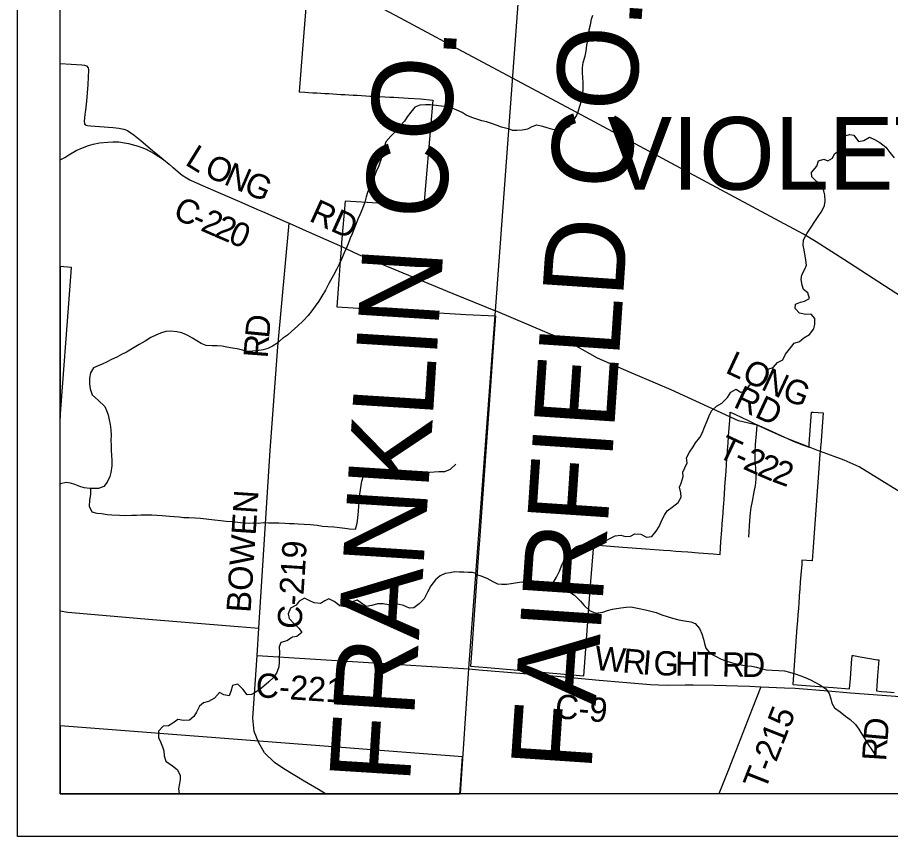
# Model space of a CAD drawing. Extents: x 0 to 34, y 0 to 26.1.
# Drawn here: x 23.417 to 25.464, y 14 to 15.919 of the extents above; entities that cross this region are included whole.
import ezdxf

# ---------------------------------------------------------------- set-up
doc = ezdxf.new("R2010")
doc.units = 0
for name, color, linetype in [('GM_X_City_Street', 7, 'Continuous'), ('GM_X_County', 7, 'Continuous'), ('GM_X_County_Road', 7, 'Continuous'), ('GM_X_County_Road_Text', 7, 'Continuous'), ('GM_X_County_Text', 7, 'Continuous'), ('GM_X_Minor_River', 7, 'Continuous'), ('GM_X_Rail_Line', 7, 'Continuous'), ('GM_X_Section', 7, 'Continuous'), ('GM_X_Township_Road', 7, 'Continuous'), ('GM_X_Township_Road_Text', 7, 'Continuous'), ('GM_X_Township_Text', 7, 'Continuous'), ('SC_Scratch1', 7, 'Continuous'), ('SH_Data', 7, 'Continuous')]:
    doc.layers.add(name, color=color, linetype=linetype)

msp = doc.modelspace()

# ---------------------------------------------------------------- linework, layer by layer
at = {"layer": 'GM_X_City_Street'}
msp.add_lwpolyline([(23.5167, 15.5856), (23.5275, 15.5913), (23.5372, 15.5973), (23.5546, 15.6077), (23.5688, 15.6139), (23.5831, 15.6192), (23.5944, 15.6223), (23.6092, 15.6255), (23.6285, 15.6274), (23.6405, 15.6279), (23.6468, 15.6278), (23.6543, 15.6276), (23.6678, 15.6258), (23.677, 15.624), (23.6914, 15.6202), (23.7, 15.6176), (23.7085, 15.6144), (23.7184, 15.6105), (23.7253, 15.6072), (23.7373, 15.6008), (23.7588, 15.5866)], dxfattribs=at)
at = {"layer": 'GM_X_County'}
msp.add_lwpolyline([(24.4552, 14.1), (24.4751, 14.3934), (24.5371, 15.232), (24.6091, 16.2057)], dxfattribs=at)
at = {"layer": 'GM_X_County_Road'}
for p, q in [((23.9427, 15.4854), (23.9798, 15.4693)), ((23.9729, 14.4892), (23.9827, 14.4886)), ((23.9789, 14.4244), (23.9827, 14.4886))]:
    msp.add_line(p, q, dxfattribs=at)
for points in [[(23.5167, 15.8117), (23.5427, 15.8097), (23.5679, 15.8082), (23.5738, 15.8073), (23.5787, 15.8057), (23.5822, 15.8013), (23.5836, 15.7969), (23.5813, 15.762), (23.5784, 15.7235), (23.5764, 15.7025), (23.5745, 15.6926), (23.5736, 15.6834), (23.5733, 15.6767), (23.5739, 15.6699), (23.5751, 15.668), (23.5774, 15.6668), (23.581, 15.6665), (23.5877, 15.6657), (23.6412, 15.6612), (23.6542, 15.6597), (23.6663, 15.6576), (23.675, 15.6543), (23.6903, 15.6433), (23.7058, 15.6311), (23.7337, 15.6071), (23.7452, 15.5979), (23.7588, 15.5866)], [(23.7588, 15.5866), (23.772, 15.5755), (23.7801, 15.5687), (23.7817, 15.5674)], [(23.7817, 15.5674), (23.7938, 15.5575), (23.8028, 15.5499), (23.813, 15.5432), (23.8207, 15.5387), (23.8225, 15.5379)], [(23.8225, 15.5379), (23.8519, 15.5249), (23.9427, 15.4854)], [(23.9798, 15.4693), (23.9909, 15.4644), (24.0442, 15.4416)], [(23.9827, 14.4886), (24.0095, 14.9049), (24.0268, 15.1479), (24.0533, 15.4376)], [(24.0442, 15.4416), (24.0533, 15.4376), (24.1005, 15.4166), (24.1786, 15.3816), (24.1865, 15.3779)], [(24.1865, 15.3779), (24.2164, 15.3641), (24.4376, 15.2722), (24.5373, 15.2315)], [(23.5167, 14.5285), (23.5349, 14.5261), (23.7336, 14.5085), (23.9345, 14.4919), (23.9729, 14.4892)], [(24.089, 14.1299), (24.0411, 14.1588), (24.0194, 14.1733), (23.996, 14.1964), (23.9824, 14.2199), (23.9717, 14.2463), (23.9682, 14.2777), (23.9789, 14.4244)], [(23.9789, 14.4244), (24.2271, 14.4084), (24.4753, 14.3929)], [(24.4753, 14.3929), (24.4981, 14.391), (24.5942, 14.3831), (24.681, 14.3757), (24.7801, 14.3668), (24.8359, 14.3619), (24.901, 14.356), (24.9197, 14.3551), (24.9415, 14.3549), (24.9819, 14.3557), (25.0005, 14.3558), (25.0503, 14.3545), (25.1341, 14.3521), (25.1593, 14.351), (25.2149, 14.3487), (25.2397, 14.3475), (25.3171, 14.3416), (25.3699, 14.3371), (25.4863, 14.3285)], [(24.1387, 14.1), (24.1223, 14.1099), (24.0981, 14.1245), (24.089, 14.1299)]]:
    msp.add_lwpolyline(points, dxfattribs=at)
at = {"layer": 'GM_X_Minor_River'}
for points in [[(24.5694, 15.6581), (24.5769, 15.6553), (24.5871, 15.6555), (24.6, 15.6557), (24.6132, 15.6582), (24.6232, 15.6637), (24.6342, 15.6678), (24.6478, 15.6649), (24.6602, 15.6606), (24.6711, 15.6574), (24.6847, 15.6561), (24.6969, 15.6574), (24.7102, 15.6641), (24.7183, 15.6742), (24.7276, 15.6889), (24.7315, 15.6991), (24.7363, 15.7142), (24.7391, 15.7255), (24.742, 15.7414), (24.7429, 15.7517), (24.743, 15.7653), (24.7421, 15.7794), (24.7415, 15.7889), (24.7413, 15.8014), (24.743, 15.8139), (24.7474, 15.8286), (24.7502, 15.8407), (24.7519, 15.8544), (24.7543, 15.8657), (24.7556, 15.8763), (24.7569, 15.89), (24.7598, 15.9021), (24.7626, 15.915), (24.7658, 15.9248)], [(24.5694, 15.6581), (24.5641, 15.659), (24.5513, 15.6624), (24.5415, 15.6659), (24.5279, 15.6709), (24.5162, 15.6748), (24.5052, 15.6775), (24.4939, 15.681), (24.4818, 15.6849), (24.469, 15.6903), (24.4589, 15.6964), (24.4464, 15.7025), (24.4328, 15.7083), (24.4207, 15.7107), (24.4098, 15.7115), (24.3981, 15.7127), (24.3852, 15.7143), (24.3735, 15.7148), (24.3599, 15.7141), (24.3481, 15.7092), (24.339, 15.6975), (24.3306, 15.6862), (24.3237, 15.6764), (24.315, 15.6658), (24.3051, 15.6548), (24.2921, 15.6409), (24.2807, 15.6277), (24.2761, 15.6156), (24.2734, 15.6057), (24.2714, 15.5958), (24.2679, 15.583), (24.2637, 15.572), (24.258, 15.5587), (24.2534, 15.5478), (24.2465, 15.5338), (24.2419, 15.522), (24.2372, 15.5088), (24.2345, 15.4993), (24.2307, 15.4868), (24.2257, 15.472), (24.2191, 15.4569), (24.2145, 15.4463), (24.2099, 15.4342), (24.2053, 15.4228), (24.2011, 15.4122), (24.1969, 15.402), (24.1919, 15.3891), (24.1876, 15.3778), (24.183, 15.3676), (24.1765, 15.3532), (24.1708, 15.3411), (24.1643, 15.329), (24.1574, 15.3154), (24.1467, 15.2957), (24.1386, 15.2802), (24.1306, 15.2662), (24.123, 15.2545), (24.1146, 15.2428), (24.107, 15.2318), (24.0982, 15.2208), (24.0864, 15.2084), (24.0735, 15.1956), (24.0601, 15.1839), (24.0495, 15.1752), (24.0381, 15.167), (24.0244, 15.1553), (24.0149, 15.1489), (24.0039, 15.1436), (23.9929, 15.1403), (23.9782, 15.1381), (23.968, 15.1374), (23.9551, 15.1367), (23.9445, 15.1398), (23.9321, 15.1429), (23.9211, 15.1445), (23.9079, 15.1469), (23.8966, 15.1492), (23.8852, 15.1501), (23.8735, 15.1498), (23.8588, 15.1506), (23.8474, 15.1552), (23.8369, 15.1614), (23.8267, 15.1675), (23.8158, 15.174), (23.8022, 15.1806), (23.7905, 15.1829), (23.7754, 15.1841), (23.7644, 15.1831), (23.7519, 15.1794), (23.7409, 15.1745), (23.7295, 15.1696), (23.7163, 15.1606), (23.7018, 15.1527), (23.6867, 15.1433), (23.6722, 15.1351), (23.6609, 15.1298), (23.6495, 15.1235), (23.637, 15.1175), (23.6252, 15.1115), (23.6153, 15.1066), (23.6055, 15.1029)], [(25.2542, 15.3055), (25.2555, 15.3165), (25.2625, 15.3293), (25.2668, 15.3391), (25.2651, 15.3509), (25.2633, 15.3604), (25.2612, 15.3737), (25.2591, 15.3855), (25.2593, 15.3984), (25.2679, 15.4138), (25.2775, 15.4277), (25.286, 15.4409), (25.2938, 15.4529), (25.3023, 15.4657), (25.3089, 15.4789), (25.3102, 15.4891), (25.3092, 15.5028), (25.3064, 15.5165), (25.3024, 15.5261), (25.2904, 15.5353), (25.2788, 15.5461), (25.2782, 15.556), (25.2905, 15.571), (25.2945, 15.5835), (25.307, 15.5871), (25.3168, 15.5836), (25.3279, 15.5899), (25.3322, 15.5997), (25.3425, 15.6067), (25.3484, 15.6188), (25.35, 15.6286), (25.354, 15.6415), (25.3677, 15.6451), (25.3775, 15.6438), (25.3882, 15.6285), (25.4008, 15.6314), (25.4141, 15.6391), (25.4258, 15.6333), (25.4389, 15.6267), (25.4524, 15.6155), (25.4617, 15.6032), (25.4725, 15.5901)], [(24.4921, 14.6163), (24.4928, 14.6142), (24.503, 14.6111), (24.5169, 14.6056), (24.5312, 14.5978), (24.5424, 14.5923), (24.5526, 14.591), (24.5629, 14.5916), (24.5742, 14.5926), (24.5837, 14.5944), (24.5993, 14.5965), (24.6098, 14.5933), (24.62, 14.5897), (24.6309, 14.5877), (24.6438, 14.5863), (24.6578, 14.5869), (24.6719, 14.5928), (24.6804, 14.6079), (24.6878, 14.6222), (24.6941, 14.6384), (24.7011, 14.652), (24.7069, 14.6618), (24.7177, 14.6726), (24.7276, 14.6793), (24.7371, 14.683), (24.7473, 14.6844), (24.7595, 14.6857), (24.7708, 14.6874), (24.7841, 14.6899), (24.7948, 14.6924), (24.8054, 14.698), (24.818, 14.705), (24.8309, 14.7063), (24.8426, 14.7028), (24.8543, 14.7037), (24.8639, 14.7093), (24.8779, 14.7087), (24.8914, 14.7013), (24.9043, 14.7031), (24.9143, 14.7154), (24.9213, 14.7267), (24.9279, 14.7426), (24.9334, 14.7528), (24.94, 14.7633), (24.9514, 14.7719), (24.9656, 14.7827), (24.973, 14.7955), (24.972, 14.8054), (24.9691, 14.8183), (24.973, 14.8281), (24.9771, 14.844), (24.9768, 14.8535), (24.9811, 14.8637), (24.9866, 14.8757), (24.9852, 14.8875), (24.9922, 14.9007), (25.0007, 14.9131), (25.0066, 14.9229), (25.0162, 14.9349), (25.0216, 14.9455), (25.0275, 14.9594), (25.0334, 14.9738), (25.0381, 14.9859), (25.0439, 14.9972), (25.0558, 15.0084), (25.0681, 15.0158), (25.0811, 15.0285), (25.0889, 15.0413), (25.1018, 15.048), (25.1116, 15.041), (25.1245, 15.0442), (25.1341, 15.0585), (25.1474, 15.0603), (25.1572, 15.0563), (25.166, 15.0668), (25.1719, 15.0812), (25.1763, 15.0948), (25.1888, 15.0988), (25.1985, 15.1108), (25.2114, 15.1174), (25.2173, 15.1306), (25.2265, 15.1423), (25.2373, 15.1558), (25.2499, 15.1602), (25.2602, 15.1684), (25.2736, 15.1765), (25.284, 15.1897), (25.286, 15.2003), (25.2862, 15.2143), (25.2773, 15.2243), (25.2648, 15.223), (25.2504, 15.2266), (25.2404, 15.2377), (25.2405, 15.2472), (25.2523, 15.252), (25.2618, 15.2545), (25.2736, 15.2608), (25.27, 15.2738), (25.2599, 15.2822), (25.2563, 15.2918), (25.2542, 15.3055)], [(23.6055, 15.1029), (23.5949, 15.098), (23.5876, 15.0866), (23.5853, 15.0738), (23.5856, 15.0612), (23.5874, 15.0491), (23.5922, 15.035), (23.6069, 15.022), (23.6212, 15.0079), (23.6256, 14.998), (23.629, 14.9881), (23.6319, 14.9767), (23.6341, 14.9653), (23.6359, 14.9532), (23.6362, 14.9399), (23.6354, 14.9285), (23.6361, 14.9163), (23.6364, 14.9065), (23.6371, 14.8924), (23.6378, 14.8826), (23.6377, 14.8685), (23.6357, 14.8534), (23.633, 14.8435), (23.6269, 14.8303), (23.6192, 14.8204), (23.6067, 14.8152), (23.5867, 14.8153), (23.5727, 14.8173), (23.5629, 14.8204), (23.5512, 14.8247), (23.541, 14.8278), (23.5312, 14.8293), (23.5179, 14.8268), (23.5167, 14.8257)], [(23.5878, 14.8153), (23.5881, 14.8017), (23.5854, 14.7884), (23.5849, 14.7744), (23.5909, 14.7607), (23.6026, 14.7576), (23.6139, 14.7567), (23.6275, 14.7547), (23.6377, 14.7535), (23.6559, 14.7527), (23.6691, 14.7526), (23.6846, 14.7529), (23.696, 14.7532), (23.7069, 14.7535), (23.7202, 14.7542), (23.7319, 14.7541), (23.7436, 14.7529), (23.7561, 14.7524), (23.7731, 14.7504), (23.7837, 14.7496), (23.7958, 14.7488), (23.8064, 14.7479), (23.8188, 14.7475), (23.8332, 14.747), (23.8453, 14.7458), (23.8593, 14.7442), (23.8789, 14.7418), (23.8937, 14.7402), (23.9061, 14.739), (23.9209, 14.7385), (23.933, 14.7369), (23.9462, 14.7353), (23.9583, 14.7345), (23.9697, 14.7348), (23.981, 14.7347), (23.9939, 14.7358), (24.0052, 14.7353), (24.0298, 14.7352), (24.0434, 14.7347), (24.0544, 14.7339), (24.0646, 14.7334), (24.0744, 14.733), (24.0891, 14.7321), (24.1035, 14.7309), (24.119, 14.7293), (24.1318, 14.7273), (24.1447, 14.7265), (24.1583, 14.7256), (24.1715, 14.724), (24.184, 14.7224), (24.1953, 14.7212), (24.2089, 14.7204), (24.2132, 14.734), (24.2148, 14.7462), (24.216, 14.7625), (24.2168, 14.775), (24.2184, 14.7879), (24.2197, 14.8023), (24.2208, 14.8122), (24.2228, 14.8228), (24.2244, 14.833), (24.2282, 14.8451), (24.243, 14.8526), (24.2544, 14.8533), (24.265, 14.8525), (24.2752, 14.852), (24.3103, 14.8518), (24.3228, 14.8525), (24.3463, 14.8524), (24.3603, 14.8527), (24.3731, 14.8533), (24.3833, 14.8537), (24.3939, 14.8543), (24.4049, 14.855), (24.4189, 14.8557), (24.4322, 14.8606), (24.4443, 14.8722)], [(24.4921, 14.6163), (24.4832, 14.6189), (24.473, 14.619), (24.4632, 14.6194), (24.453, 14.6198), (24.4416, 14.6199), (24.431, 14.6181), (24.4193, 14.6163), (24.4079, 14.611), (24.3969, 14.6016), (24.3862, 14.5876), (24.3782, 14.5729), (24.3702, 14.557), (24.3584, 14.5453), (24.3458, 14.5359), (24.336, 14.5348), (24.3217, 14.541), (24.3084, 14.5445), (24.2967, 14.5423), (24.2869, 14.5431), (24.2737, 14.5454), (24.2604, 14.5451), (24.2472, 14.541), (24.2339, 14.5388), (24.2128, 14.5542), (24.1992, 14.5493), (24.1851, 14.5384), (24.1727, 14.5404), (24.1591, 14.5511), (24.147, 14.5568), (24.1372, 14.5527), (24.1269, 14.5463), (24.1126, 14.5476), (24.1024, 14.5522), (24.09, 14.5583), (24.0774, 14.5516), (24.0698, 14.5418), (24.0565, 14.5354), (24.0512, 14.5221), (24.0534, 14.5111), (24.0654, 14.4985), (24.0774, 14.4878), (24.083, 14.4779), (24.072, 14.4685), (24.0618, 14.4671), (24.0485, 14.4588), (24.0345, 14.4547), (24.0306, 14.4449), (24.0309, 14.4304), (24.0305, 14.4191), (24.03, 14.4092), (24.0296, 14.3978), (24.0246, 14.3846), (24.0166, 14.3728), (24.0063, 14.3627), (23.9892, 14.3476), (23.9759, 14.3382), (23.9653, 14.3326), (23.9554, 14.3322), (23.9449, 14.3452), (23.9333, 14.3574), (23.9208, 14.3537), (23.9169, 14.3397), (23.9131, 14.3298), (23.9002, 14.3322), (23.8901, 14.3372), (23.879, 14.3244), (23.8646, 14.3161), (23.8529, 14.3135), (23.8433, 14.3052), (23.8365, 14.2912), (23.8303, 14.281), (23.8201, 14.2727), (23.8057, 14.2721), (23.7925, 14.2741), (23.7807, 14.2654), (23.7708, 14.2594), (23.758, 14.2583), (23.7477, 14.2466), (23.7476, 14.2322), (23.7521, 14.2219), (23.7565, 14.2102), (23.7595, 14.2006), (23.7609, 14.1889), (23.7647, 14.1763), (23.7801, 14.166), (23.7914, 14.1568), (23.7981, 14.1439), (23.7984, 14.134), (23.7965, 14.1245), (23.7945, 14.1116), (23.7955, 14.1)], [(24.6719, 14.5928), (24.6872, 14.5835), (24.6981, 14.578), (24.7117, 14.5729), (24.7229, 14.5659), (24.7367, 14.5517), (24.7457, 14.5417), (24.7576, 14.5297), (24.7723, 14.5238), (24.789, 14.5259), (24.8, 14.5295), (24.8114, 14.5324), (24.8209, 14.5342), (24.8311, 14.5359), (24.8436, 14.5373), (24.855, 14.5379), (24.8746, 14.5346), (24.889, 14.5313), (24.9018, 14.5281), (24.9142, 14.5249), (24.9278, 14.5198), (24.9527, 14.5119), (24.967, 14.5079), (24.9806, 14.5054), (24.9957, 14.5029), (25.0058, 14.499), (25.0159, 14.4871), (25.021, 14.4749), (25.0254, 14.4623), (25.0275, 14.452), (25.0307, 14.4417), (25.0408, 14.4291), (25.0547, 14.4217), (25.0667, 14.4158), (25.0772, 14.4115), (25.0897, 14.4079), (25.1025, 14.4043), (25.1176, 14.4014), (25.1278, 14.4001), (25.1384, 14.3989), (25.1493, 14.3968), (25.1599, 14.3936), (25.1731, 14.3904), (25.1863, 14.3895), (25.2018, 14.3893), (25.2147, 14.3879), (25.2264, 14.3855), (25.2399, 14.3811), (25.2535, 14.3764), (25.2636, 14.3725), (25.2757, 14.367), (25.2862, 14.3615), (25.2978, 14.3553), (25.3121, 14.3464), (25.3195, 14.3349), (25.3235, 14.3223), (25.326, 14.3128), (25.3323, 14.3017), (25.3454, 14.292), (25.3581, 14.2824), (25.3686, 14.2739), (25.3813, 14.2623), (25.3894, 14.2516), (25.3965, 14.2401), (25.4035, 14.229), (25.4113, 14.216), (25.4194, 14.203), (25.4272, 14.1915)]]:
    msp.add_lwpolyline(points, dxfattribs=at)
at = {"layer": 'GM_X_Rail_Line'}
for points in [[(24.5774, 15.7768), (24.4384, 15.8515), (24.315, 15.9174), (24.1803, 15.9897), (24.1325, 16.0154), (24.0479, 16.0609), (24.0177, 16.0785), (23.9935, 16.0947), (23.9701, 16.1123), (23.9224, 16.1522), (23.896, 16.175), (23.8622, 16.2036), (23.8327, 16.2287), (23.7982, 16.2582)], [(27.301, 14.1), (27.0785, 14.2427), (26.9137, 14.3485), (26.2475, 14.7771), (25.9542, 14.966), (25.6567, 15.1572), (25.4759, 15.2734), (25.3538, 15.3521), (25.2892, 15.3938), (25.2593, 15.4116), (25.1825, 15.4531), (24.7379, 15.6913), (24.5774, 15.7768)]]:
    msp.add_lwpolyline(points, dxfattribs=at)
at = {"layer": 'GM_X_Section'}
for points in [[(23.5167, 15.3356), (23.5167, 14.9804), (23.5397, 15.28), (23.5437, 15.3334)], [(23.5167, 14.2597), (23.5167, 14.1), (24.4538, 14.1), (24.4604, 14.1871)]]:
    msp.add_lwpolyline(points, close=True, dxfattribs=at)
at = {"layer": 'GM_X_Township_Road'}
for points in [[(25.0782, 14.9877), (25.0361, 15.0068), (24.9494, 15.0464), (24.8555, 15.0869), (24.7767, 15.1208), (24.7043, 15.1619), (24.6588, 15.1804), (24.5373, 15.2315)], [(25.2715, 14.9128), (25.2407, 14.9247), (25.2149, 14.9354), (25.1866, 14.9478), (25.1512, 14.9638), (25.1073, 14.9745), (25.0782, 14.9877)], [(25.1317, 14.7018), (25.134, 14.7402), (25.1355, 14.7587), (25.1371, 14.771), (25.1396, 14.7862), (25.1441, 14.8075), (25.1471, 14.8227), (25.1479, 14.8289), (25.1487, 14.8383), (25.1487, 14.8477), (25.1477, 14.8632), (25.1466, 14.8817), (25.1464, 14.9003), (25.1472, 14.9189), (25.149, 14.9436), (25.1512, 14.9638)], [(25.2995, 14.902), (25.2985, 14.9023), (25.2715, 14.9128)], [(25.5202, 14.7858), (25.4431, 14.8332), (25.3898, 14.8663), (25.3549, 14.8818), (25.2995, 14.902)], [(25.1593, 14.351), (25.1394, 14.299), (25.1008, 14.2007), (25.0828, 14.1545), (25.061, 14.1)]]:
    msp.add_lwpolyline(points, dxfattribs=at)
at = {"layer": 'SC_Scratch1'}
msp.add_lwpolyline([(24.0966, 15.9919), (24.0851, 15.8452), (24.0772, 15.7447), (24.0902, 15.744), (24.0994, 15.7435), (24.1089, 15.7429), (24.1183, 15.7424), (24.1278, 15.7418), (24.1372, 15.7413), (24.1467, 15.7408), (24.1564, 15.7402), (24.1656, 15.7397), (24.175, 15.7392), (24.1845, 15.7386), (24.1939, 15.7381), (24.2034, 15.7376), (24.2129, 15.737), (24.2233, 15.7365), (24.2337, 15.7359), (24.2431, 15.7353), (24.2526, 15.7348), (24.263, 15.7342), (24.2782, 15.7334), (24.29, 15.7327), (24.2994, 15.7322), (24.3325, 15.7303), (24.3614, 15.7287), (24.3907, 15.7253), (24.3852, 15.6618), (24.3716, 15.5068), (24.3691, 15.4781), (24.3332, 15.4802), (24.2844, 15.483), (24.2365, 15.4858), (24.1848, 15.4888), (24.1765, 15.392), (24.1765, 15.3898), (24.1756, 15.3768), (24.1734, 15.3481), (24.1727, 15.3376), (24.1702, 15.3043), (24.1654, 15.2412), (24.2038, 15.239), (24.2394, 15.2369), (24.2718, 15.235), (24.3008, 15.2333), (24.3248, 15.2319), (24.3488, 15.2305), (24.3768, 15.2288), (24.4306, 15.2257), (24.4677, 15.2235), (24.5375, 15.2198), (24.5323, 15.1467), (24.5266, 15.0671), (24.5007, 14.7047), (24.4978, 14.6645), (24.48, 14.4184), (24.4786, 14.3993), (24.5179, 14.396), (24.7449, 14.3768), (24.7605, 14.5881), (24.7676, 14.6836), (24.7676, 14.6838), (24.7681, 14.6838), (24.8363, 14.6784), (24.8898, 14.6742), (24.9316, 14.6711), (24.947, 14.6699), (24.9473, 14.6699), (24.9605, 14.6689), (24.9737, 14.668), (24.988, 14.6669), (24.998, 14.6661), (25.0045, 14.6657), (25.0137, 14.665), (25.0478, 14.6624), (25.0639, 14.6612), (25.065, 14.6763), (25.0661, 14.691), (25.068, 14.718), (25.0691, 14.7323), (25.0691, 14.7325), (25.0709, 14.7579), (25.0711, 14.7609), (25.0726, 14.7808), (25.0726, 14.7812), (25.0732, 14.7892), (25.0743, 14.8041), (25.0752, 14.8175), (25.0754, 14.8191), (25.0768, 14.8393), (25.0773, 14.8459), (25.0774, 14.847), (25.0775, 14.8482), (25.0776, 14.8498), (25.0779, 14.854), (25.0781, 14.8573), (25.0783, 14.8604), (25.0789, 14.8678), (25.0789, 14.8683), (25.0793, 14.8742), (25.0801, 14.8845), (25.0814, 14.9025), (25.0816, 14.905), (25.0822, 14.9132), (25.0828, 14.9222), (25.0839, 14.9374), (25.0847, 14.9479), (25.0854, 14.9573), (25.0873, 14.9842), (25.0875, 14.9865), (25.0876, 14.9883), (25.0878, 14.9906), (25.088, 14.9943), (25.0968, 14.9902), (25.1168, 14.9808), (25.1265, 14.9762), (25.1456, 14.9673), (25.1473, 14.9665), (25.1494, 14.9655), (25.1545, 14.9632), (25.1564, 14.9623), (25.1686, 14.9568), (25.186, 14.9489), (25.2147, 14.9358), (25.2238, 14.9317), (25.2351, 14.9265), (25.2593, 14.9174), (25.2725, 14.9124), (25.2731, 14.9203), (25.2785, 14.9943), (25.2825, 14.9941), (25.3054, 14.9926), (25.2998, 14.9168), (25.2996, 14.9143), (25.2994, 14.9111), (25.2988, 14.9034), (25.2982, 14.8952), (25.2814, 14.668), (25.2798, 14.6461), (25.279, 14.6461), (25.2559, 14.6474), (25.2553, 14.6383), (25.2534, 14.6129), (25.2521, 14.5958), (25.251, 14.5804), (25.2497, 14.564), (25.2492, 14.5574), (25.2488, 14.552), (25.2483, 14.5467), (25.2476, 14.5356), (25.2475, 14.534), (25.2465, 14.5205), (25.2454, 14.5056), (25.2443, 14.4903), (25.2343, 14.3564), (25.3066, 14.3507), (25.3293, 14.349), (25.3675, 14.346), (25.3694, 14.37), (25.373, 14.4168), (25.3733, 14.4206), (25.3736, 14.4243), (25.3764, 14.4239), (25.3927, 14.4211), (25.4148, 14.4173), (25.4287, 14.415), (25.4331, 14.4142), (25.436, 14.4137), (25.4331, 14.3768), (25.4304, 14.3411), (25.4428, 14.3402), (25.4552, 14.3392), (25.4719, 14.3379)], dxfattribs=at)
at = {"layer": 'SH_Data'}
for points in [[(23.4167, 21), (30.4167, 21), (30.4167, 14), (23.4167, 14)], [(23.5167, 20.9), (30.3167, 20.9), (30.3167, 14.1), (23.5167, 14.1)]]:
    msp.add_lwpolyline(points, close=True, dxfattribs=at)

# ---------------------------------------------------------------- texts
at = {"layer": 'GM_X_County_Road_Text'}
for s, height, rotation, p in [('L', 0.0568, 328.1954, (23.8072, 15.5758)), ('O', 0.0568, 337.1343, (23.8519, 15.549)), ('N', 0.0568, 336.5986, (23.8979, 15.5296)), ('G', 0.0568, 336.5953, (23.9438, 15.5098)), ('C', 0.0568, 335.1126, (23.7783, 15.4508)), ('RD', 0.05682, 335.6372, (24.0979, 15.4434)), ('2', 0.0568, 336.6098, (23.8435, 15.4211)), ('2', 0.0568, 336.7665, (23.8757, 15.4071)), ('-', 0.0568, 336.3058, (23.8218, 15.4306)), ('0', 0.0568, 336.7982, (23.9079, 15.3933)), ('D', 0.0568, 84.4652, (24.0065, 15.1661)), ('R', 0.0568, 85.7692, (24.0031, 15.1199)), ('BOWEN', 0.05682, 86.2604, (23.9631, 14.5236)), ('C-219', 0.05682, 86.4074, (24.0823, 14.4852)), ('W', 0.0568, 354.7109, (24.768, 14.3908)), ('R', 0.0568, 354.7364, (24.8336, 14.3847)), ('I', 0.0568, 355.0852, (24.8804, 14.3804)), ('G', 0.0568, 358.5756, (24.9074, 14.3782)), ('H', 0.0568, 359.0437, (24.9579, 14.3769)), ('T', 0.0568, 359.0459, (25.0079, 14.3761)), ('R', 0.0568, 359.0455, (25.0679, 14.3751)), ('D', 0.0568, 359.0455, (25.1146, 14.3743)), ('C-221', 0.05682, 356.1494, (23.9738, 14.327)), ('C-9', 0.05682, 354.9719, (24.6755, 14.2777))]:
    msp.add_text(s, height=height, rotation=rotation, dxfattribs=at).set_placement(p)
at = {"layer": 'GM_X_County_Text'}
for s, rotation, p in [('FAIRFIELD CO.', 86.1646, (24.7619, 14.1516)), ('FRANKLIN CO.', 86.3996, (24.3365, 14.1228))]:
    msp.add_text(s, height=0.189394, rotation=rotation, dxfattribs=at).set_placement(p)
at = {"layer": 'GM_X_Township_Road_Text'}
for s, height, rotation, p in [('L', 0.0568, 335.0058, (25.0737, 15.088)), ('O', 0.0568, 335.0007, (25.1122, 15.0701)), ('N', 0.0568, 335.058, (25.1575, 15.0489)), ('G', 0.0568, 338.2778, (25.2061, 15.0265)), ('RD', 0.05682, 334.9831, (25.0928, 15.0075)), ('T', 0.0568, 334.8821, (25.0548, 14.8909)), ('2', 0.0568, 335.6564, (25.1152, 14.8627)), ('-', 0.0568, 335.0508, (25.0934, 14.8728)), ('2', 0.0568, 336.928, (25.1483, 14.8477)), ('2', 0.0568, 339.6753, (25.1833, 14.8329)), ('T-215', 0.05682, 68.5613, (25.1692, 14.1057)), ('D', 0.0568, 84.9263, (25.4563, 14.2218)), ('R', 0.0568, 86.3092, (25.4533, 14.1756))]:
    msp.add_text(s, height=height, rotation=rotation, dxfattribs=at).set_placement(p)
at = {"layer": 'GM_X_Township_Text'}
msp.add_text('VIOLET', height=0.17045, rotation=0, dxfattribs=at).set_placement((24.7995, 15.5156))

doc.saveas('drawing.dxf')
